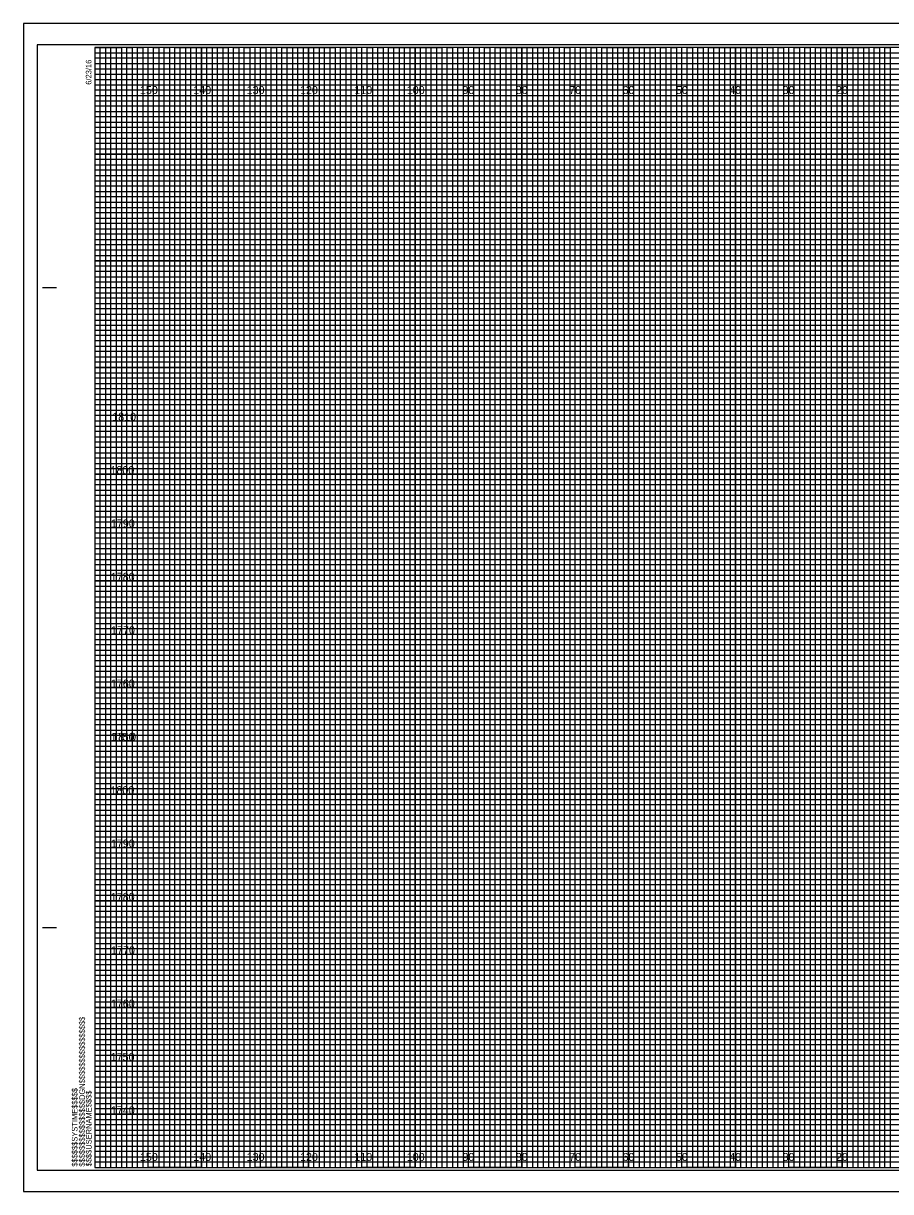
# Model space of a CAD drawing. Extents: x -15 to 323, y -5 to 6170.
# Drawn here: x -13.4 to 149.1, y 1975.5 to 2194.5 of the extents above; entities that cross this region are included whole.
import ezdxf

# ---------------------------------------------------------------- set-up
doc = ezdxf.new("R2010")
doc.units = 0
for name, color, linetype in [('Prop XS DDE', 7, 'Continuous'), ('Prop XS DDE Slope Text', 7, 'Continuous'), ('Prop XS DDE Text', 7, 'Continuous'), ('Prop XS Earthwork Shape', 7, 'Continuous'), ('Prop XS Noise Wall', 7, 'Continuous'), ('Prop XS Retaining Wall', 7, 'Continuous'), ('Prop XS Station Labels', 7, 'Continuous'), ('Scratch_Level_3', 7, 'Continuous'), ('Scratch_Level_7', 7, 'Continuous'), ('Scratch_Level_8', 7, 'Continuous'), ('Sheet Cross Section Grid Minor 1 CELL', 7, 'Continuous')]:
    doc.layers.add(name, color=color, linetype=linetype)

msp = doc.modelspace()

# ---------------------------------------------------------------- linework, layer by layer
at = {"layer": 'Prop XS DDE'}
msp.add_lwpolyline([(-13.4, 1975.5), (323.3, 1975.5), (323.3, 2194.5), (-13.4, 2194.5)], close=True, dxfattribs=at)
at = {"layer": 'Prop XS DDE Slope Text'}
msp.add_lwpolyline([(-10.8, 1979.5), (322.4, 1979.5), (322.4, 2190.5), (-10.8, 2190.5)], close=True, dxfattribs=at)
at = {"layer": 'Prop XS DDE Text'}
for p, q in [((10, 1980), (10, 2190)), ((20, 1980), (20, 2190)), ((30, 1980), (30, 2190)), ((40, 1980), (40, 2190)), ((50, 1980), (50, 2190)), ((60, 1980), (60, 2190)), ((70, 1980), (70, 2190)), ((80, 1980), (80, 2190)), ((90, 1980), (90, 2190)), ((100, 1980), (100, 2190)), ((110, 1980), (110, 2190)), ((120, 1980), (120, 2190)), ((130, 1980), (130, 2190)), ((140, 1980), (140, 2190)), ((0, 2180), (320, 2180)), ((0, 2170), (320, 2170)), ((0, 2160), (320, 2160)), ((0, 2150), (320, 2150)), ((0, 2140), (320, 2140)), ((0, 2130), (320, 2130)), ((0, 2120), (320, 2120)), ((0, 2110), (320, 2110)), ((0, 2100), (320, 2100)), ((0, 2090), (320, 2090)), ((0, 2080), (320, 2080)), ((0, 2070), (320, 2070)), ((0, 2060), (320, 2060)), ((0, 2050), (320, 2050)), ((0, 2040), (320, 2040)), ((0, 2030), (320, 2030)), ((0, 2020), (320, 2020)), ((0, 2010), (320, 2010)), ((0, 2000), (320, 2000)), ((0, 1990), (320, 1990))]:
    msp.add_line(p, q, dxfattribs=at)
at = {"layer": 'Prop XS Earthwork Shape'}
for p, q in [((10, 2190), (0, 2190)), ((10, 1980), (10, 2190)), ((30, 2190), (20, 2190)), ((20, 2190), (20, 1980)), ((30, 1980), (30, 2190)), ((50, 2190), (40, 2190)), ((40, 2190), (40, 1980)), ((50, 1980), (50, 2190)), ((70, 2190), (60, 2190)), ((60, 2190), (60, 1980)), ((70, 1980), (70, 2190)), ((90, 2190), (80, 2190)), ((80, 2190), (80, 1980)), ((90, 1980), (90, 2190)), ((110, 2190), (100, 2190)), ((100, 2190), (100, 1980)), ((110, 1980), (110, 2190)), ((130, 2190), (120, 2190)), ((120, 2190), (120, 1980)), ((130, 1980), (130, 2190)), ((150, 2190), (140, 2190)), ((140, 2190), (140, 1980)), ((20, 1980), (10, 1980)), ((40, 1980), (30, 1980)), ((60, 1980), (50, 1980)), ((80, 1980), (70, 1980)), ((100, 1980), (90, 1980)), ((120, 1980), (110, 1980)), ((140, 1980), (130, 1980))]:
    msp.add_line(p, q, dxfattribs=at)
for points in [[(0, 2180), (320, 2180), (320, 2170), (0, 2170)], [(0, 2160), (320, 2160), (320, 2150), (0, 2150)], [(0, 2140), (320, 2140), (320, 2130), (0, 2130)], [(0, 2120), (320, 2120), (320, 2110), (0, 2110)], [(0, 2100), (320, 2100), (320, 2090), (0, 2090)], [(0, 2080), (320, 2080), (320, 2070), (0, 2070)], [(0, 2060), (320, 2060), (320, 2050), (0, 2050)], [(0, 2040), (320, 2040), (320, 2030), (0, 2030)], [(0, 2020), (320, 2020), (320, 2010), (0, 2010)], [(0, 2000), (320, 2000), (320, 1990), (0, 1990)]]:
    msp.add_lwpolyline(points, dxfattribs=at)
at = {"layer": 'Prop XS Noise Wall'}
for p, q in [((-9.8, 2145), (-7.3, 2145)), ((-9.7, 2145), (-7.2, 2145)), ((-9.8, 2025), (-7.3, 2025)), ((-9.7, 2025), (-7.2, 2025)), ((0, 1980), (0, 1980)), ((0, 1980), (0, 1980)), ((0, 1980), (0, 1980)), ((0, 1980), (0, 1980)), ((0, 1980), (0, 1980)), ((0, 1980), (0, 1980)), ((0, 1980), (0, 1980))]:
    msp.add_line(p, q, dxfattribs=at)
msp.add_lwpolyline([(320, 2190), (0, 2190), (0, 1980), (320, 1980)], close=True, dxfattribs=at)
at = {"layer": 'Prop XS Retaining Wall'}
for points in [[(0, 1980), (1, 1980), (1, 2190), (2, 2190), (2, 1980)], [(2, 1980), (3, 1980), (3, 2190), (4, 2190), (4, 1980)], [(5, 1980), (6, 1980), (6, 2190), (7, 2190), (7, 1980)], [(7, 1980), (8, 1980), (8, 2190), (9, 2190), (9, 1980)], [(10, 1980), (11, 1980), (11, 2190), (12, 2190), (12, 1980)], [(12, 1980), (13, 1980), (13, 2190), (14, 2190), (14, 1980)], [(15, 1980), (16, 1980), (16, 2190), (17, 2190), (17, 1980)], [(17, 1980), (18, 1980), (18, 2190), (19, 2190), (19, 1980)], [(20, 1980), (21, 1980), (21, 2190), (22, 2190), (22, 1980)], [(22, 1980), (23, 1980), (23, 2190), (24, 2190), (24, 1980)], [(25, 1980), (26, 1980), (26, 2190), (27, 2190), (27, 1980)], [(27, 1980), (28, 1980), (28, 2190), (29, 2190), (29, 1980)], [(30, 1980), (31, 1980), (31, 2190), (32, 2190), (32, 1980)], [(32, 1980), (33, 1980), (33, 2190), (34, 2190), (34, 1980)], [(35, 1980), (36, 1980), (36, 2190), (37, 2190), (37, 1980)], [(37, 1980), (38, 1980), (38, 2190), (39, 2190), (39, 1980)], [(40, 1980), (41, 1980), (41, 2190), (42, 2190), (42, 1980)], [(42, 1980), (43, 1980), (43, 2190), (44, 2190), (44, 1980)], [(45, 1980), (46, 1980), (46, 2190), (47, 2190), (47, 1980)], [(47, 1980), (48, 1980), (48, 2190), (49, 2190), (49, 1980)], [(50, 1980), (51, 1980), (51, 2190), (52, 2190), (52, 1980)], [(52, 1980), (53, 1980), (53, 2190), (54, 2190), (54, 1980)], [(55, 1980), (56, 1980), (56, 2190), (57, 2190), (57, 1980)], [(57, 1980), (58, 1980), (58, 2190), (59, 2190), (59, 1980)], [(60, 1980), (61, 1980), (61, 2190), (62, 2190), (62, 1980)], [(62, 1980), (63, 1980), (63, 2190), (64, 2190), (64, 1980)], [(65, 1980), (66, 1980), (66, 2190), (67, 2190), (67, 1980)], [(67, 1980), (68, 1980), (68, 2190), (69, 2190), (69, 1980)], [(70, 1980), (71, 1980), (71, 2190), (72, 2190), (72, 1980)], [(72, 1980), (73, 1980), (73, 2190), (74, 2190), (74, 1980)], [(75, 1980), (76, 1980), (76, 2190), (77, 2190), (77, 1980)], [(77, 1980), (78, 1980), (78, 2190), (79, 2190), (79, 1980)], [(80, 1980), (81, 1980), (81, 2190), (82, 2190), (82, 1980)], [(82, 1980), (83, 1980), (83, 2190), (84, 2190), (84, 1980)], [(85, 1980), (86, 1980), (86, 2190), (87, 2190), (87, 1980)], [(87, 1980), (88, 1980), (88, 2190), (89, 2190), (89, 1980)], [(90, 1980), (91, 1980), (91, 2190), (92, 2190), (92, 1980)], [(92, 1980), (93, 1980), (93, 2190), (94, 2190), (94, 1980)], [(95, 1980), (96, 1980), (96, 2190), (97, 2190), (97, 1980)], [(97, 1980), (98, 1980), (98, 2190), (99, 2190), (99, 1980)], [(100, 1980), (101, 1980), (101, 2190), (102, 2190), (102, 1980)], [(102, 1980), (103, 1980), (103, 2190), (104, 2190), (104, 1980)], [(105, 1980), (106, 1980), (106, 2190), (107, 2190), (107, 1980)], [(107, 1980), (108, 1980), (108, 2190), (109, 2190), (109, 1980)], [(110, 1980), (111, 1980), (111, 2190), (112, 2190), (112, 1980)], [(112, 1980), (113, 1980), (113, 2190), (114, 2190), (114, 1980)], [(115, 1980), (116, 1980), (116, 2190), (117, 2190), (117, 1980)], [(117, 1980), (118, 1980), (118, 2190), (119, 2190), (119, 1980)], [(120, 1980), (121, 1980), (121, 2190), (122, 2190), (122, 1980)], [(122, 1980), (123, 1980), (123, 2190), (124, 2190), (124, 1980)], [(125, 1980), (126, 1980), (126, 2190), (127, 2190), (127, 1980)], [(127, 1980), (128, 1980), (128, 2190), (129, 2190), (129, 1980)], [(130, 1980), (131, 1980), (131, 2190), (132, 2190), (132, 1980)], [(132, 1980), (133, 1980), (133, 2190), (134, 2190), (134, 1980)], [(135, 1980), (136, 1980), (136, 2190), (137, 2190), (137, 1980)], [(137, 1980), (138, 1980), (138, 2190), (139, 2190), (139, 1980)], [(140, 1980), (141, 1980), (141, 2190), (142, 2190), (142, 1980)], [(142, 1980), (143, 1980), (143, 2190), (144, 2190), (144, 1980)], [(145, 1980), (146, 1980), (146, 2190), (147, 2190), (147, 1980)], [(147, 1980), (148, 1980), (148, 2190), (149, 2190), (149, 1980)]]:
    msp.add_lwpolyline(points, dxfattribs=at)
at = {"layer": 'Prop XS Station Labels'}
for points in [[(0, 2190), (5, 2190), (5, 1980), (15, 1980), (15, 2190), (25, 2190), (25, 1980), (35, 1980), (35, 2190), (45, 2190), (45, 1980), (55, 1980), (55, 2190), (65, 2190), (65, 1980), (75, 1980), (75, 2190), (85, 2190), (85, 1980), (95, 1980), (95, 2190), (105, 2190), (105, 1980), (115, 1980), (115, 2190), (125, 2190), (125, 1980), (135, 1980), (135, 2190), (145, 2190), (145, 1980), (155, 1980)], [(0, 2185), (275, 2185)], [(0, 2165), (320, 2165), (320, 2175), (0, 2175)], [(0, 2145), (320, 2145), (320, 2155), (0, 2155)], [(0, 2125), (320, 2125), (320, 2135), (0, 2135)], [(0, 2105), (320, 2105), (320, 2115), (0, 2115)], [(0, 2085), (320, 2085), (320, 2095), (0, 2095)], [(0, 2065), (320, 2065), (320, 2075), (0, 2075)], [(0, 2045), (320, 2045), (320, 2055), (0, 2055)], [(0, 2025), (320, 2025), (320, 2035), (0, 2035)], [(0, 2005), (320, 2005), (320, 2015), (0, 2015)], [(0, 1985), (320, 1985), (320, 1995), (0, 1995)]]:
    msp.add_lwpolyline(points, dxfattribs=at)
at = {"layer": 'Scratch_Level_7'}
for p, q in [((323.3, 2194.5), (-13.4, 2194.5)), ((-13.4, 2194.5), (-13.4, 1975.5)), ((-13.4, 1975.5), (323.3, 1975.5))]:
    msp.add_line(p, q, dxfattribs=at)
at = {"layer": 'Sheet Cross Section Grid Minor 1 CELL'}
for p, q in [((0, 2189), (260, 2189)), ((260, 2187.98), (0, 2187.98)), ((0, 2187.98), (0, 2187)), ((0, 2187), (260, 2187)), ((260, 2185.89), (0, 2185.89)), ((0, 2185.89), (0, 2184)), ((0, 2184), (320, 2184))]:
    msp.add_line(p, q, dxfattribs=at)
for points in [[(0, 2183), (270, 2183), (320, 2183), (320, 2182), (0, 2182)], [(0, 2181), (320, 2181), (320, 2179), (0, 2179)], [(0, 2178), (320, 2178), (320, 2177), (0, 2176.98)], [(0, 2176), (320, 2176), (320, 2174), (0, 2174)], [(0, 2173), (320, 2173), (320, 2172), (0, 2172)], [(0, 2171), (320, 2171), (320, 2169), (0, 2169)], [(0, 2168), (320, 2168), (320, 2167), (0, 2167)], [(0, 2166), (320, 2166), (320, 2164), (0, 2164)], [(0, 2163), (320, 2163), (320, 2162), (0, 2162)], [(0, 2161), (320, 2161), (320, 2159), (0, 2159)], [(0, 2158), (320, 2158), (320, 2157), (0, 2157)], [(0, 2156), (320, 2156), (320, 2153.95), (320, 2153), (320, 2152), (0, 2152)], [(0, 2154), (320, 2154), (320, 2153), (0, 2153)], [(0, 2151), (320, 2151), (320, 2149), (0, 2149.03)], [(0, 2149.03), (320, 2149), (320, 2148), (0, 2148)], [(0, 2147), (320, 2147), (320, 2146), (0, 2146)], [(0, 2144), (320, 2144), (320, 2143), (0, 2143)], [(0, 2142), (320, 2142), (320, 2141), (0, 2141)], [(-0.07, 2138.89), (320, 2138.89), (320, 2137.88), (-0.07, 2137.88)], [(0, 2137), (320, 2137), (320, 2136), (0, 2136)], [(0, 2134), (320, 2134), (320, 2133), (0, 2133)], [(0, 2132), (320, 2132), (320, 2131), (0, 2131)], [(0, 2129), (320, 2129), (320, 2128), (0, 2128)], [(0, 2127), (320, 2127), (320, 2126), (0, 2126)], [(0, 2124), (320, 2124), (320, 2123), (0, 2123)], [(0, 2122), (320, 2122), (320, 2121), (0, 2121)], [(0, 2119), (320, 2119), (319.99, 2117.98), (0, 2118)], [(0, 2117), (320, 2117), (320, 2116), (0, 2116)], [(0, 2114), (320, 2114), (320, 2113), (0, 2113)], [(0, 2112), (320, 2112), (320, 2111), (0, 2111)], [(0, 2109), (320, 2109), (320, 2108), (0, 2108)], [(0, 2107), (320, 2107), (320, 2106), (0, 2106)], [(0, 2104), (320, 2104), (320, 2103), (0, 2103)], [(0, 2102), (320, 2102), (320, 2101), (0, 2101)], [(0, 2099), (320, 2099), (320, 2098), (0, 2098)], [(0, 2096.99), (320.07, 2096.91), (320, 2096), (0, 2096)], [(0, 2094), (320, 2094), (320, 2093), (0, 2093)], [(0, 2092), (320, 2092), (320, 2091), (0, 2091)], [(0, 2089), (320, 2089), (320, 2088), (0, 2088)], [(0, 2087), (320, 2087), (320, 2086), (0, 2086)], [(0, 2084), (320, 2084), (320, 2083), (0, 2083)], [(0, 2082), (320, 2082), (320, 2081), (0, 2081)], [(0, 2079), (320, 2079), (320, 2078), (0, 2078)], [(0, 2077), (320, 2077), (320, 2076), (0, 2076)], [(0, 2074), (320, 2074), (320, 2073), (0, 2073)], [(0, 2072), (320, 2072), (320, 2071), (0, 2071)], [(0, 2069), (320, 2069), (320, 2068), (0, 2068)], [(0, 2067), (320, 2067), (320, 2066), (0, 2066)], [(0, 2064), (320, 2064), (320, 2063), (0, 2063)], [(0, 2062), (320, 2062), (320, 2061), (0, 2061)], [(0, 2059), (320, 2059), (319.99, 2057.98), (0, 2058)], [(0, 2057), (320, 2057), (320, 2056), (0, 2056)], [(0, 2054), (320, 2054), (320, 2053), (0, 2053)], [(0, 2052), (320, 2052), (320, 2051), (0, 2051)], [(0, 2049), (320, 2049), (320, 2048), (0, 2048)], [(0, 2047), (320, 2047), (320, 2046), (0, 2046)], [(0, 2044), (320, 2044), (320, 2043), (0, 2043)], [(0, 2042), (320, 2042), (320, 2041), (0, 2041)], [(0, 2039), (320, 2039), (320, 2038), (0, 2038)], [(0, 2036.99), (320.07, 2036.91), (320, 2036), (0, 2036)], [(0, 2034), (320, 2034), (320, 2033), (0, 2033)], [(0, 2032), (320, 2032), (320, 2031), (0, 2031)], [(0, 2029), (320, 2029), (320, 2028), (0, 2028)], [(0, 2027), (320, 2027), (320, 2026), (0, 2026)], [(0, 2024), (320, 2024), (320, 2023), (0, 2023)], [(0, 2022), (320, 2022), (320, 2021), (0, 2021)], [(0, 2019), (320, 2019), (320, 2018), (0, 2018)], [(0, 2017), (320, 2017), (320, 2016), (0, 2016)], [(0, 2014), (320, 2014), (320, 2013), (0, 2013)], [(0, 2012), (320, 2012), (320, 2011), (0, 2011)], [(0, 2009), (320, 2009), (320, 2008), (0, 2008)], [(0, 2007), (320, 2007), (320, 2006), (0, 2006)], [(0, 2004), (320, 2004), (320, 2003), (0, 2003)], [(0, 2002), (320, 2002), (320, 2001), (0, 2001)], [(0, 1999), (320, 1999), (320, 1998), (0, 1998)], [(0, 1997), (320, 1997), (320, 1996), (0, 1996)], [(0, 1994), (320, 1994), (320, 1993), (0, 1993)], [(0, 1992), (320, 1992), (320, 1991), (0, 1991)], [(0, 1989), (320, 1989), (320, 1988), (0, 1988)], [(0, 1987), (320, 1987), (320, 1986), (0, 1986)], [(0, 1984), (320, 1984), (320, 1983), (0, 1983)], [(0, 1982), (320, 1982), (320, 1981), (0, 1981)]]:
    msp.add_lwpolyline(points, dxfattribs=at)

# ---------------------------------------------------------------- texts
at = {"layer": 'Prop XS Noise Wall'}
for s, p in [('6/23/16', (-0.65, 2183)), ('$$$$$$$$$$$$$$$$DGN$$$$$$$$$$$$$$$$', (-1.88, 1980.18)), ('$$$$$$SYSTIME$$$$$', (-3.26, 1980.18)), ('$$$$USERNAME$$$$', (-0.62, 1980.23))]:
    msp.add_text(s, height=1.05, rotation=90, dxfattribs=at).set_placement(p)
at = {"layer": 'Scratch_Level_3'}
for s, p in [('1810', (3.25, 2120)), ('1800', (2.92, 2110)), ('1790', (3, 2100)), ('1780', (2.98, 2090)), ('1770', (3.04, 2080)), ('1760', (3, 2070)), ('1750', (2.96, 2060)), ('1810', (3.25, 2060)), ('1800', (2.92, 2050)), ('1790', (3, 2040)), ('1780', (2.98, 2030)), ('1770', (3.04, 2020)), ('1760', (3, 2010)), ('1750', (2.96, 2000)), ('1740', (3, 1990))]:
    msp.add_text(s, height=1.5, dxfattribs=at).set_placement(p)
at = {"layer": 'Scratch_Level_8'}
for s, p in [('150', (8.44, 2181.25)), ('140', (18.44, 2181.25)), ('130', (28.44, 2181.25)), ('120', (38.44, 2181.25)), ('110', (48.62, 2181.25)), ('100', (58.44, 2181.25)), ('90', (68.86, 2181.25)), ('80', (78.86, 2181.25)), ('70', (88.86, 2181.25)), ('60', (98.86, 2181.25)), ('50', (108.86, 2181.25)), ('40', (118.86, 2181.25)), ('30', (128.86, 2181.25)), ('20', (138.86, 2181.25)), ('150', (8.44, 1981.25)), ('140', (18.44, 1981.25)), ('130', (28.44, 1981.25)), ('120', (38.44, 1981.25)), ('110', (48.62, 1981.25)), ('100', (58.44, 1981.25)), ('90', (68.86, 1981.25)), ('80', (78.86, 1981.25)), ('70', (88.86, 1981.25)), ('60', (98.86, 1981.25)), ('50', (108.86, 1981.25)), ('40', (118.86, 1981.25)), ('30', (128.86, 1981.25)), ('20', (138.86, 1981.25))]:
    msp.add_text(s, height=1.5, dxfattribs=at).set_placement(p)

doc.saveas('drawing.dxf')
